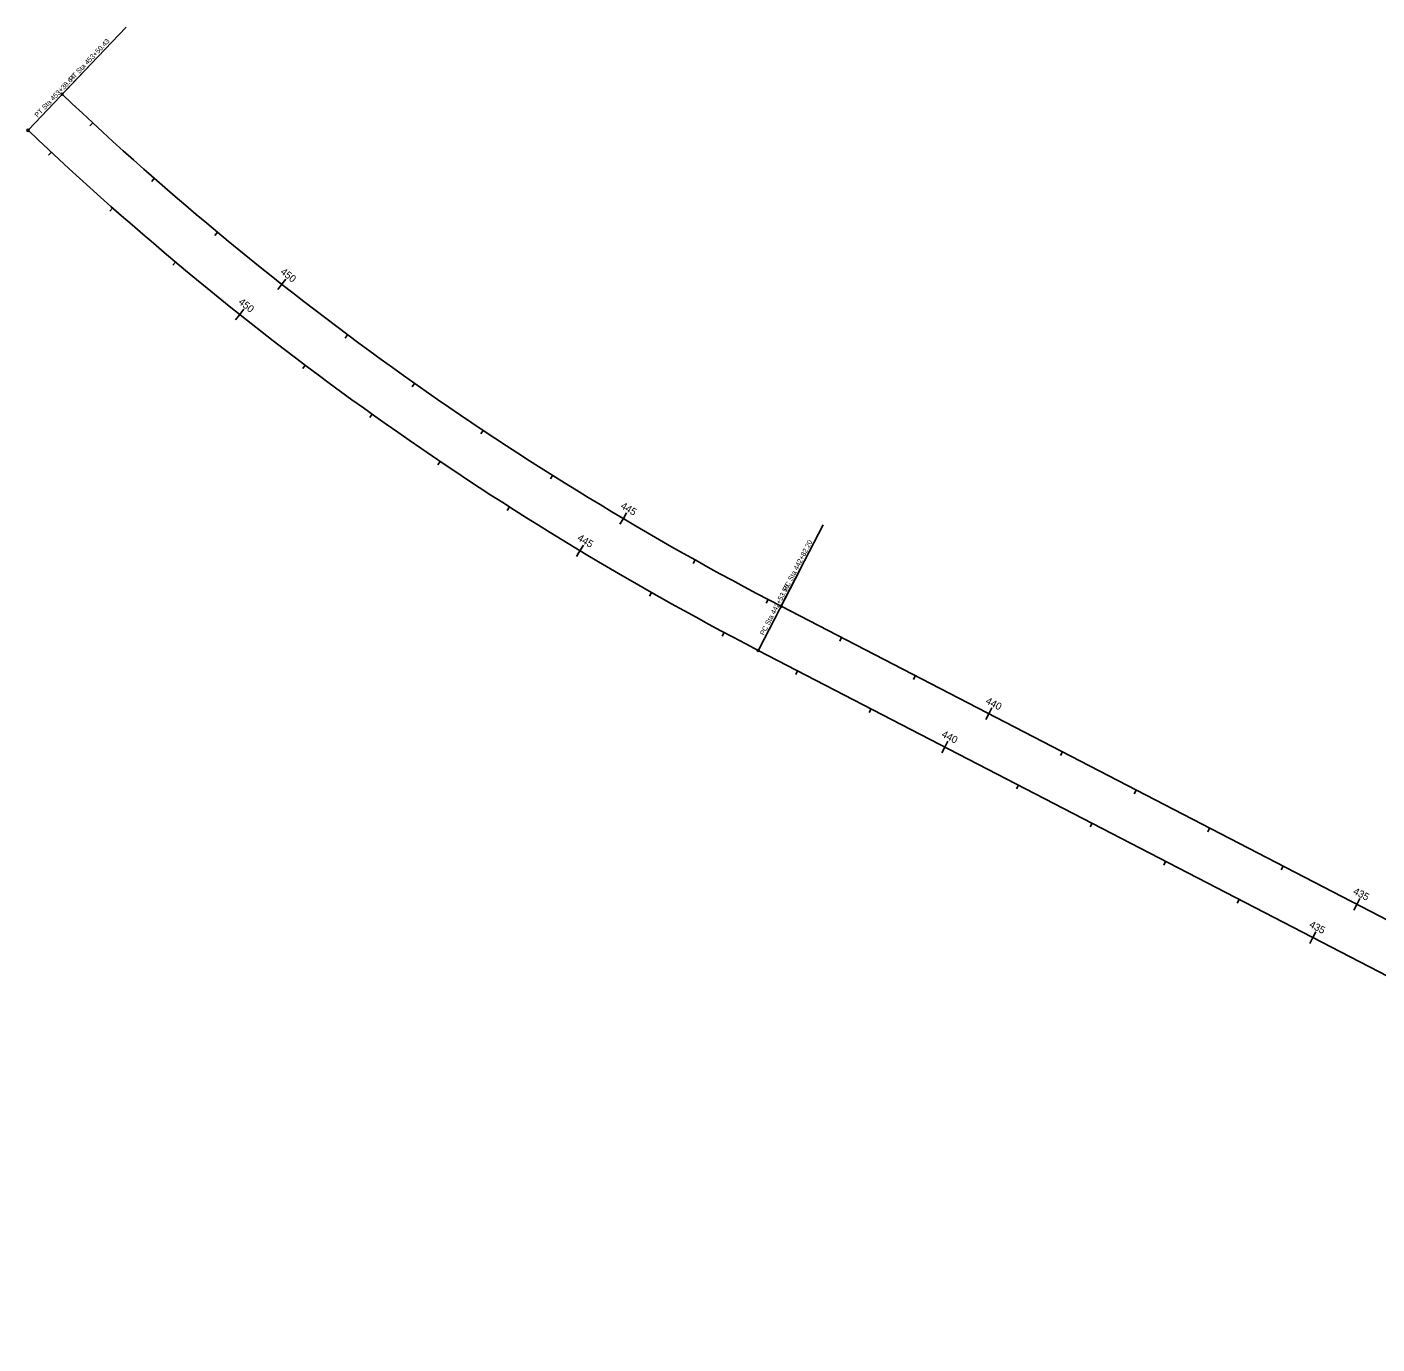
# Model space of a CAD drawing. Extents: x 1602163 to 1612907, y 1087635 to 1096265.
# Drawn here: x 1605880 to 1607509, y 1094677 to 1096265 of the extents above; entities that cross this region are included whole.
import ezdxf

# ---------------------------------------------------------------- set-up
doc = ezdxf.new("R2010")
doc.units = 0
for name, color, linetype in [('RD_HC_Cl', 7, 'Continuous'), ('RD_HC_Data_Tic', 7, 'Continuous'), ('RD_HC_Points', 7, 'Continuous'), ('RD_HC_TX_Sta50', 7, 'Continuous')]:
    doc.layers.add(name, color=color, linetype=linetype)

msp = doc.modelspace()

# ---------------------------------------------------------------- linework, layer by layer
at = {"layer": 'RD_HC_Cl'}
for p, q in [((1608405.8, 1094730), (1606790, 1095566.6)), ((1608378.1, 1094676.8), (1606762.4, 1095513.3))]:
    msp.add_line(p, q, dxfattribs=at)
for radius in [3789.7, 3849.7]:
    msp.add_arc((1608532.4, 1098932), radius, 226.4765, 242.6268, dxfattribs=at)
at = {"layer": 'RD_HC_Data_Tic'}
for p, q in [((1605959.4, 1096149.6), (1605956, 1096145.9)), ((1605909.5, 1096114.1), (1605906.1, 1096110.5)), ((1606033.7, 1096082.7), (1606030.5, 1096078.9)), ((1605983.6, 1096046.9), (1605980.2, 1096043.2)), ((1606109.8, 1096017.8), (1606106.6, 1096013.9)), ((1606059.3, 1095981.7), (1606056.1, 1095977.9)), ((1606187.5, 1095954.9), (1606182.6, 1095948.6)), ((1606187.5, 1095954.9), (1606192.5, 1095961.1)), ((1606136.8, 1095918.5), (1606141.8, 1095924.7)), ((1606136.8, 1095918.5), (1606131.8, 1095912.2)), ((1606266.9, 1095894), (1606263.9, 1095890)), ((1606215.9, 1095857.3), (1606212.9, 1095853.3)), ((1606347.8, 1095835.3), (1606345, 1095831.2)), ((1606296.5, 1095798.1), (1606293.6, 1095794.1)), ((1606430.3, 1095778.7), (1606427.5, 1095774.6)), ((1606378.7, 1095741.1), (1606375.9, 1095737)), ((1606514.2, 1095724.4), (1606511.6, 1095720.2)), ((1606462.3, 1095686.3), (1606459.6, 1095682.1)), ((1606599.6, 1095672.3), (1606603.6, 1095679.1)), ((1606599.6, 1095672.3), (1606595.5, 1095665.4)), ((1606547.3, 1095633.6), (1606543.2, 1095626.7)), ((1606547.3, 1095633.6), (1606551.4, 1095640.4)), ((1606686.2, 1095622.4), (1606683.8, 1095618)), ((1606633.6, 1095583.1), (1606631.2, 1095578.8)), ((1606774.2, 1095574.8), (1606771.9, 1095570.4)), ((1606721.2, 1095535), (1606718.9, 1095530.5)), ((1606863, 1095528.8), (1606860.7, 1095524.4)), ((1606809.9, 1095488.7), (1606807.6, 1095484.3)), ((1606951.8, 1095482.8), (1606949.5, 1095478.4)), ((1606898.7, 1095442.8), (1606896.4, 1095438.3)), ((1607040.6, 1095436.9), (1607036.9, 1095429.8)), ((1607040.6, 1095436.9), (1607044.3, 1095444)), ((1606987.5, 1095396.8), (1606991.2, 1095403.9)), ((1606987.5, 1095396.8), (1606983.8, 1095389.7)), ((1607129.4, 1095390.9), (1607127.1, 1095386.4)), ((1607076.3, 1095350.8), (1607074, 1095346.4)), ((1607218.2, 1095344.9), (1607215.9, 1095340.5)), ((1607165.1, 1095304.8), (1607162.8, 1095300.4)), ((1607307, 1095298.9), (1607304.7, 1095294.5)), ((1607253.9, 1095258.8), (1607251.6, 1095254.4)), ((1607395.8, 1095252.9), (1607393.5, 1095248.5)), ((1607342.7, 1095212.9), (1607340.4, 1095208.4)), ((1607484.6, 1095207), (1607480.9, 1095199.9)), ((1607484.6, 1095207), (1607488.3, 1095214.1)), ((1607431.5, 1095166.9), (1607435.2, 1095174)), ((1607431.5, 1095166.9), (1607427.9, 1095159.8))]:
    msp.add_line(p, q, dxfattribs=at)
at = {"layer": 'RD_HC_Points'}
for p, q in [((1605923.5, 1096185), (1605999.7, 1096265.2)), ((1605882.2, 1096141.5), (1605958, 1096221.3)), ((1606790.6, 1095567.7), (1606840.8, 1095664.7)), ((1606763, 1095514.4), (1606813.2, 1095611.5))]:
    msp.add_line(p, q, dxfattribs=at)
for centre in [(1605922.6, 1096184.1), (1605881.3, 1096140.6), (1606790, 1095566.6), (1606762.4, 1095513.3)]:
    msp.add_circle(centre, 1.25, dxfattribs=at)

# ---------------------------------------------------------------- texts
for s, rotation, p in [('PT Sta 453+50.43', 46.4765, (1605934.1, 1096199.1)), ('PT Sta 453+38.64', 46.4765, (1605892.8, 1096155.6)), ('PC Sta 442+82.20', 62.6268, (1606796.8, 1095584.2)), ('PC Sta 442+53.50', 62.6268, (1606769.2, 1095530.9))]:
    msp.add_text(s, height=6, rotation=rotation, dxfattribs=at).set_placement(p)
at = {"layer": 'RD_HC_TX_Sta50'}
for s, rotation, p in [('450', 321.7746, (1606185.1, 1095968.5)), ('450', 321.5166, (1606134.4, 1095932.2)), ('445', 329.334, (1606595.5, 1095685.4)), ('445', 328.9582, (1606543.3, 1095646.8)), ('440', 332.6268, (1607035.9, 1095449.7)), ('440', 332.6268, (1606982.8, 1095409.6)), ('435', 332.6268, (1607479.3, 1095220.1)), ('435', 332.6268, (1607426.3, 1095180))]:
    msp.add_text(s, height=8.75, rotation=rotation, dxfattribs=at).set_placement(p)

doc.saveas('drawing.dxf')
